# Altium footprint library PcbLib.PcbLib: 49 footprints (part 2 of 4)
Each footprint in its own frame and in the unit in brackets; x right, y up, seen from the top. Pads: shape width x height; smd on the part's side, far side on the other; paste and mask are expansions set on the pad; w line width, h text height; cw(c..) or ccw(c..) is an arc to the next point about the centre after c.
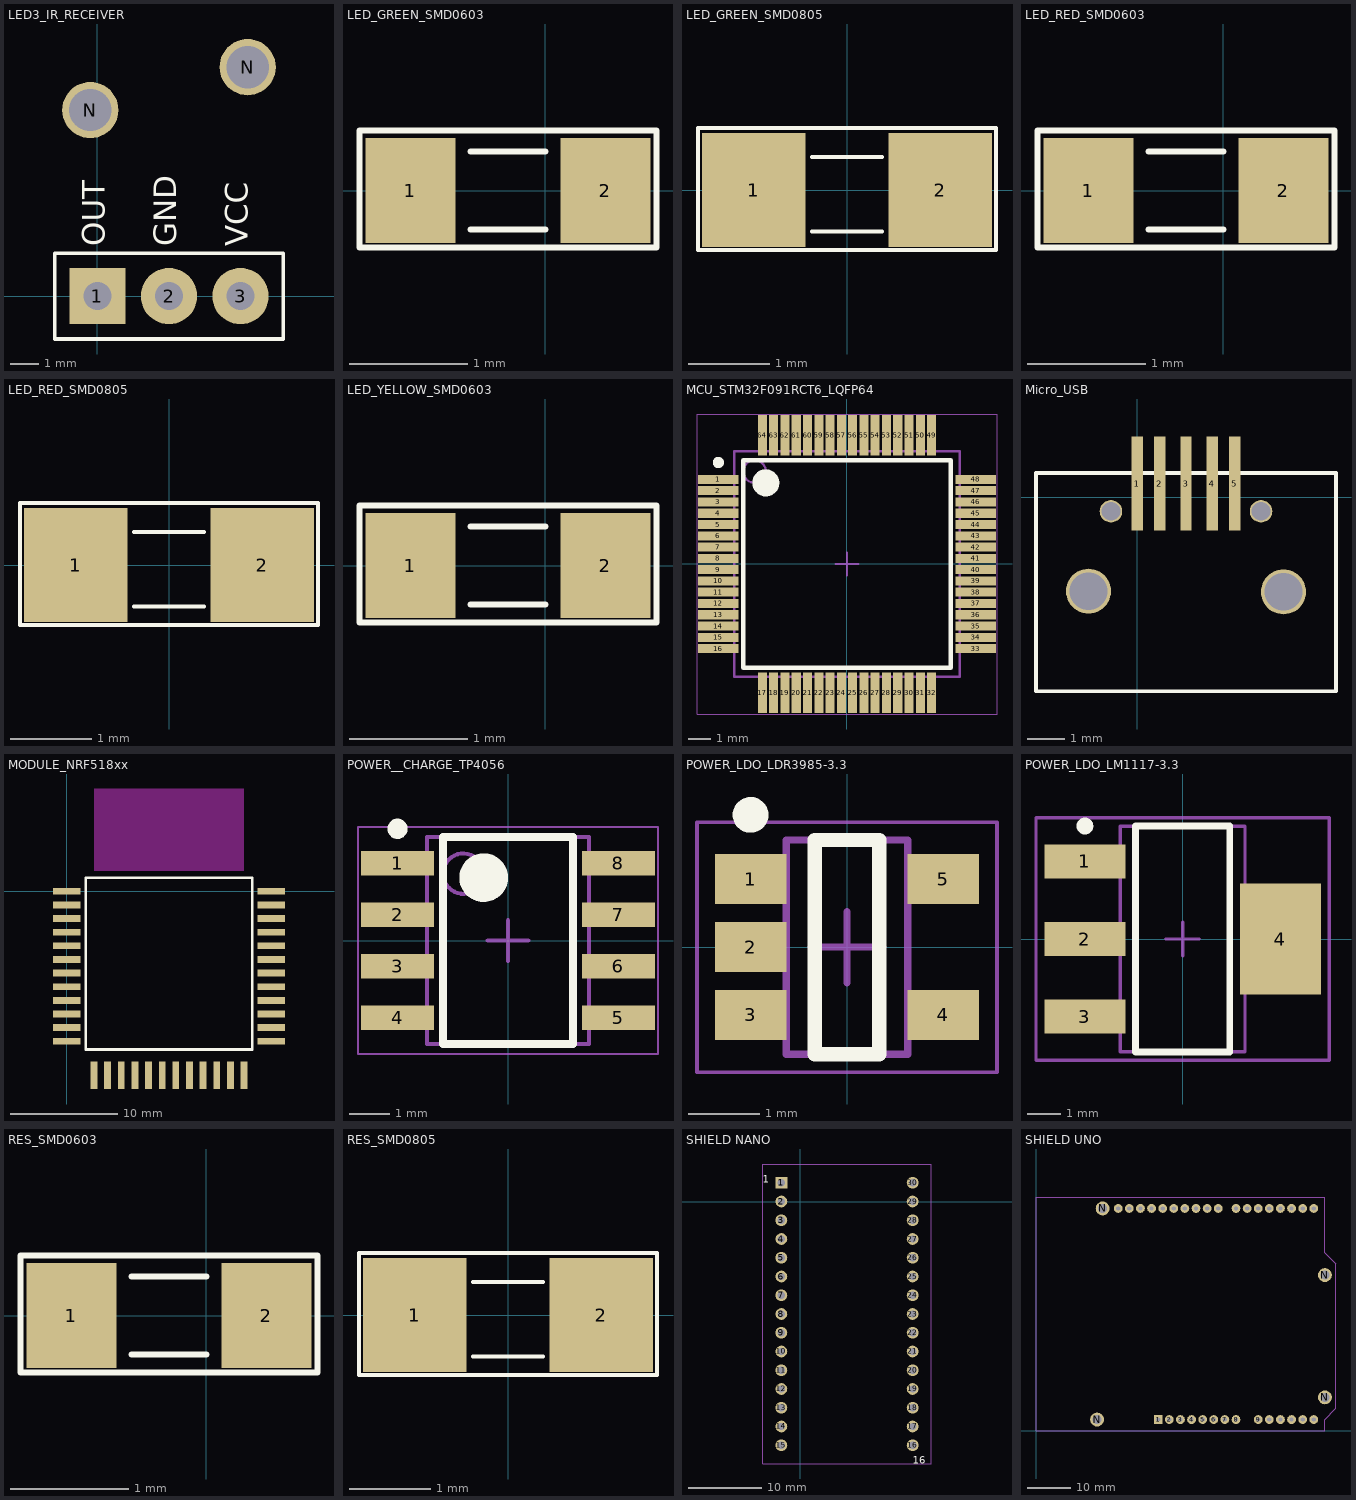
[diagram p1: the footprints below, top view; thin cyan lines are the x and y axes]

## LED3_IR_RECEIVER [mm] "HEADER, SINGLE, DISTANCE = 100mil"
pads (5):
  rect 2x2 hole 1: 1(0,0)
  round 2 hole 1: 2(2.54,0) 3(5.08,0)
  round 2 hole 1.5: N(-0.254,6.604) N(5.334,8.128)
Top Overlay:
  lines w0.127: -1.524,-1.524 6.604,-1.524 6.604,1.524 -1.524,1.524 -1.524,-1.524
  text "OUT" at 0.254,1.778 h0.8
  text "GND" at 2.794,1.778 h0.8
  text "VCC" at 5.334,1.778 h0.8
3D body "User Library-GP1UE26.step": height 7.1, standoff -3.6, extent -0.704,-0.328 6.096,9.472

## LED_GREEN_SMD0603 [mil] "Compoment SMD 60x30mil"
height 50
pads (2):
  rect 30x35 smd: 1(-45,0) 2(20,0)
Top Overlay:
  lines w2: -25,-13 0,-13 ; -25,13 0,13 ; -62,-19 -52.75,-19 -0.25,-19 37,-19 37,20 -62,20 -62,-19
3D body "User Library-LED_0603_G.STEP": height 23.62, standoff -0.08, extent -46.49,-15.74 16.51,15.75

## LED_GREEN_SMD0805 [mil] "Compoment SMD 80x50mil"
height 50
pads (2):
  rect 50x55 smd: 1(-45,0) 2(45,0)
Top Overlay:
  lines w2: -17,-20 17,-20 ; -17,16 17,16 ; -72,-29 -72,30 72,30 72,-29 -72,-29
3D body "SML-210PTT86.stp": height 31.5, standoff 0, extent -39.36,-24.6 39.38,24.61

## LED_RED_SMD0603 [mil] "Compoment SMD 60x30mil"
height 50
pads (2):
  rect 30x35 smd: 1(-45,0) 2(20,0)
Top Overlay:
  lines w2: -25,-13 0,-13 ; -25,13 0,13 ; -62,-19 -62,20 37,20 37,-19 -0.25,-19 -52.75,-19 -62,-19
3D body "User Library-LED_0603_R.STEP": height 23.62, standoff -0.08, extent -46.49,-15.74 16.51,15.75

## LED_RED_SMD0805 [mil] "Compoment SMD 80x50mil"
height 50
pads (2):
  rect 50x55 smd: 1(-45,0) 2(45,0)
Top Overlay:
  lines w2: -17,-20 17,-20 ; -17,16 17,16 ; -72,-29 72,-29 72,30 -72,30 -72,-29
3D body "User Library-CHIPLED-0805.step": height 35.43, standoff -0.39, extent -41.34,-26.57 41.34,26.58

## LED_YELLOW_SMD0603 [mil] "Compoment SMD 60x30mil"
height 50
pads (2):
  rect 30x35 smd: 1(-45,0) 2(20,0)
Top Overlay:
  lines w2: -25,-13 0,-13 ; -25,13 0,13 ; -62,-19 -62,20 37,20 37,-19 -0.25,-19 -52.75,-19 -62,-19
3D body "User Library-LED_0603_Y.STEP": height 23.62, standoff -0.08, extent -46.49,-15.74 16.51,15.75

## MCU_STM32F091RCT6_LQFP64 [mm] "STM32F091RCT6 LQFP64"
height 1.6
pads (64):
  rect 1.8x0.4 smd: 1(-5.7,3.75) 2(-5.7,3.25) 3(-5.7,2.75) 4(-5.7,2.25) 5(-5.7,1.75) 6(-5.7,1.25) 7(-5.7,0.75) 8(-5.7,0.25) 9(-5.7,-0.25) 10(-5.7,-0.75) 11(-5.7,-1.25) 12(-5.7,-1.75) 13(-5.7,-2.25) 14(-5.7,-2.75) 15(-5.7,-3.25) 16(-5.7,-3.75) 33(5.7,-3.75) 34(5.7,-3.25) 35(5.7,-2.75) 36(5.7,-2.25) 37(5.7,-1.75) 38(5.7,-1.25) 39(5.7,-0.75) 40(5.7,-0.25) 41(5.7,0.25) 42(5.7,0.75) 43(5.7,1.25) 44(5.7,1.75) 45(5.7,2.25) 46(5.7,2.75) 47(5.7,3.25) 48(5.7,3.75)
  rect 0.4x1.8 smd: 17(-3.75,-5.7) 18(-3.25,-5.7) 19(-2.75,-5.7) 20(-2.25,-5.7) 21(-1.75,-5.7) 22(-1.25,-5.7) 23(-0.75,-5.7) 24(-0.25,-5.7) 25(0.25,-5.7) 26(0.75,-5.7) 27(1.25,-5.7) 28(1.75,-5.7) 29(2.25,-5.7) 30(2.75,-5.7) 31(3.25,-5.7) 32(3.75,-5.7) 49(3.75,5.7) 50(3.25,5.7) 51(2.75,5.7) 52(2.25,5.7) 53(1.75,5.7) 54(1.25,5.7) 55(0.75,5.7) 56(0.25,5.7) 57(-0.25,5.7) 58(-0.75,5.7) 59(-1.25,5.7) 60(-1.75,5.7) 61(-2.25,5.7) 62(-2.75,5.7) 63(-3.25,5.7) 64(-3.75,5.7)
Top Overlay:
  circle w0.6: c-3.6,3.6 r0.3
  circle w0.25: c-5.7,4.5 r0.125
  lines w0.2: -4.6,-4.6 4.6,-4.6 4.6,4.6 -4.6,4.6 -4.6,-4.6
Mechanical 13:
  circle w0.1: c-4.1,4.1 r0.5
  lines w0.1: -5,-5 5,-5 5,5 -5,5 -5,-5
Mechanical 15:
  lines w0.05: -6.65,-6.65 6.65,-6.65 6.65,6.65 -6.65,6.65 -6.65,-6.65
  lines w0.1: -0.5,0 0.5,0 ; 0,-0.5 0,0.5
3D body "User Library-LQFP64_Grid_0_5.STEP": height 1.6, standoff 0, extent -6,-6 6,6

## Micro_USB [mm]
pads (9):
  rect 0.3x2.5 smd mask+0.05: 1(0,0.37) 2(0.6,0.37) 3(1.3,0.37) 4(2,0.37) 5(2.6,0.37)
  round 1.2 hole 1 mask+0.05: ""(-1.3,-2.5) ""(3.9,-2.52)
  round 0.6 hole 0.5 mask+0.05: ""(-0.7,-0.37) ""(3.3,-0.37)
Top Overlay:
  lines w0.1: -2.7,-5.17 5.3,-5.17 5.3,0.65 -2.7,0.65 -2.7,-5.17
3D body "User Library-10104111.STEP": height 2.77, standoff -0.3, extent -3.1,-5.116 5.7,0.509

## MODULE_NRF518xx [mm] "MODULE BLE NRF51822 Madeby TUAN ANH"
pads (36):
  rect 2.54x0.635 smd: 1(0,0) 2(0,-1.27) 3(0,-2.54) 4(0,-3.81) 5(0,-5.08) 6(0,-6.35) 7(0,-7.62) 8(0,-8.89) 9(0,-10.16) 10(0,-11.43) 11(0,-12.7) 12(0,-13.97) 25(19.05,-13.97) 26(19.05,-12.7) 27(19.05,-11.43) 28(19.05,-10.16) 29(19.05,-8.89) 30(19.05,-7.62) 31(19.05,-6.35) 32(19.05,-5.08) 33(19.05,-3.81) 34(19.05,-2.54) 35(19.05,-1.27) 36(19.05,0)
  rect 0.635x2.54 smd: 13(2.54,-17.145) 14(3.81,-17.145) 15(5.08,-17.145) 16(6.35,-17.145) 17(7.62,-17.145) 18(8.89,-17.145) 19(10.16,-17.145) 20(11.43,-17.145) 21(12.7,-17.145) 22(13.97,-17.145) 23(15.24,-17.145) 24(16.51,-17.145)
Top Overlay:
  lines w0.254: 1.778,-14.732 1.778,1.27 17.272,1.27 17.272,-14.732 1.778,-14.732
Keep-Out Layer:
  region: 2.54,9.525 2.54,1.905 16.51,1.905 16.51,9.525

## POWER__CHARGE_TP4056 [mm] "SOP, 8-Leads, Body 4.90x3.90mm, Pitch 1.27mm, IPC Medium Density"
height 1.75
pads (8):
  rect 1.8x0.6 smd: 1(-2.725,1.905) 2(-2.725,0.635) 3(-2.725,-0.635) 4(-2.725,-1.905) 5(2.725,-1.905) 6(2.725,-0.635) 7(2.725,0.635) 8(2.725,1.905)
Top Overlay:
  circle w0.25: c-2.725,2.755 r0.125
  circle w0.6: c-0.6,1.55 r0.3
  lines w0.2: -1.6,-2.55 -1.6,2.55 1.6,2.55 1.6,-2.55 -1.6,-2.55
Mechanical 13:
  circle w0.1: c-1.1,1.65 r0.5
  lines w0.1: -2,-2.55 -2,2.55 2,2.55 2,-2.55 -2,-2.55
Mechanical 15:
  lines w0.05: -3.7,-2.8 -3.7,2.8 3.7,2.8 3.7,-2.8 -3.7,-2.8
  lines w0.1: -0.5,0 0.5,0 ; 0,-0.5 0,0.5
3D body "User Library-sop-8.step": height 1.6, standoff 0, extent -3.021,-2.51 3.021,2.51

## POWER_LDO_LDR3985-3.3 [mm] "SOT23, 5-Leads, Body 2.90x2.80mm, Pitch 0.95mm, IPC Medium Density"
height 0.9
pads (5):
  rect 1x0.7 smd: 1(-1.35,0.95) 2(-1.35,0) 3(-1.35,-0.95) 4(1.35,-0.95) 5(1.35,0.95)
Top Overlay:
  circle w0.25: c-1.35,1.85 r0.125
  lines w0.2: -0.45,-1.5 0.45,-1.5 0.45,1.5 -0.45,1.5 -0.45,-1.5
Mechanical 13:
  lines w0.1: -0.85,-1.5 -0.85,1.5 0.85,1.5 0.85,-1.5 -0.85,-1.5
Mechanical 15:
  lines w0.05: -2.1,-1.75 -2.1,1.75 2.1,1.75 2.1,-1.75 -2.1,-1.75
  lines w0.1: -0.5,0 0.5,0 ; 0,-0.5 0,0.5
3D body: height 0.9, standoff 0.05, extent -0.85,-1.5 0.85,1.5

## POWER_LDO_LM1117-3.3 [mm] "SOT223, 4-Leads, Body 6.5x3.5mm, Pitch 2.3mm, Lead Span 7mm, IPC Medium Density"
height 1.8
pads (4):
  rect 2.4x1 smd: 1(-2.9,2.3) 2(-2.9,0) 3(-2.9,-2.3)
  rect 2.4x3.3 smd: 4(2.9,0)
Top Overlay:
  circle w0.25: c-2.9,3.35 r0.125
  lines w0.2: -1.4,-3.35 -1.4,3.35 1.4,3.35 1.4,-3.35 -1.4,-3.35
Mechanical 13:
  lines w0.1: -1.85,-3.35 -1.85,3.35 1.85,3.35 1.85,-3.35 -1.85,-3.35
Mechanical 15:
  lines w0.1: -0.5,0 0.5,0 ; 0,-0.5 0,0.5 ; -4.35,-3.6 -4.35,3.6 4.35,3.6 4.35,-3.6 -4.35,-3.6
3D body: height 1.8, standoff 0, extent -1.85,-3.35 1.85,3.35

## RES_SMD0603 [mil] "Compoment SMD 60x30mil"
height 50
pads (2):
  rect 30x35 smd: 1(-45,0) 2(20,0)
Top Overlay:
  lines w2: -25,-13 0,-13 ; -25,13 0,13 ; -62,-19 -52.75,-19 -0.25,-19 37,-19 37,20 -62,20 -62,-19
3D body "SW3DPS-RESISTOR 0603-DEFAULT.STEP": height 18.9, standoff -1.18, extent -46.49,-16.92 16.51,16.93

## RES_SMD0805 [mil] "Compoment SMD 80x50mil"
height 50
pads (2):
  rect 50x55 smd: 1(-45,0) 2(45,0)
Top Overlay:
  lines w2: -17,-20 17,-20 ; -17,16 17,16 ; -72,-29 -72,30 72,30 72,-29 -72,-29
3D body "SW3dPS-smt_resistor_packages.STEP": height 24.02, standoff -0.39, extent -39.76,-27 39.77,23

## SHIELD NANO [mm]
pads (30):
  rect 1.6x1.6 hole 1: 1(-2.54,2.54)
  round 1.6 hole 1: 2(-2.54,0) 3(-2.54,-2.54) 4(-2.54,-5.08) 5(-2.54,-7.62) 6(-2.54,-10.16) 7(-2.54,-12.7) 8(-2.54,-15.24) 9(-2.54,-17.78) 10(-2.54,-20.32) 11(-2.54,-22.86) 12(-2.54,-25.4) 13(-2.54,-27.94) 14(-2.54,-30.48) 15(-2.54,-33.02) 16(15.24,-33.02) 17(15.24,-30.48) 18(15.24,-27.94) 19(15.24,-25.4) 20(15.24,-22.86) 21(15.24,-20.32) 22(15.24,-17.78) 23(15.24,-15.24) 24(15.24,-12.7) 25(15.24,-10.16) 26(15.24,-7.62) 27(15.24,-5.08) 28(15.24,-2.54) 29(15.24,0) 30(15.24,2.54)
Top Overlay:
  text "16" at 15.24,-35.56 h1
  text "1" at -5.08,2.54 h1
Mechanical 1:
  lines w0.1: -5.08,-35.56 17.78,-35.56 17.78,5.08 -5.08,5.08 -5.08,-35.56

## SHIELD UNO [mm]
pads (36):
  rect 2x2 hole 1: 1(27.94,2.54)
  round 2 hole 1: 2(30.48,2.54) 3(33.02,2.54) 4(35.56,2.54) 5(38.1,2.54) 6(40.64,2.54) 7(43.18,2.54) 8(45.72,2.54) 9(50.8,2.54) 10(53.34,2.54) 11(55.88,2.54) 12(58.42,2.54) 13(60.96,2.54) 14(63.5,2.54) 15(63.5,50.8) 16(60.96,50.8) 17(58.42,50.8) 18(55.88,50.8) 19(53.34,50.8) 20(50.8,50.8) 21(48.26,50.8) 22(45.72,50.8) 23(41.656,50.8) 24(39.116,50.8) 25(36.576,50.8) 26(34.036,50.8) 27(31.496,50.8) 28(28.956,50.8) 29(26.416,50.8) 30(23.876,50.8) 31(21.336,50.8) 32(18.796,50.8)
  round 3.175 hole 2.032: N(13.97,2.54) N(15.24,50.8) N(66.04,7.62) N(66.04,35.56)
Mechanical 1:
  lines w0.254: 0,0 0,2.54 0,53.34 66.04,53.34 66.04,50.8 66.04,40.64 68.58,38.1 68.58,5.08 66.04,2.54 66.04,0 0,0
